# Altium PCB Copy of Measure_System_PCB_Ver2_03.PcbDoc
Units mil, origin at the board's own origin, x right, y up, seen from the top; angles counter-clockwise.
Board outline 6000 x 4000 mil, 2 copper layers (Top Layer, Bottom Layer); 49 components, 31 nets, 143 pads, 5 vias.
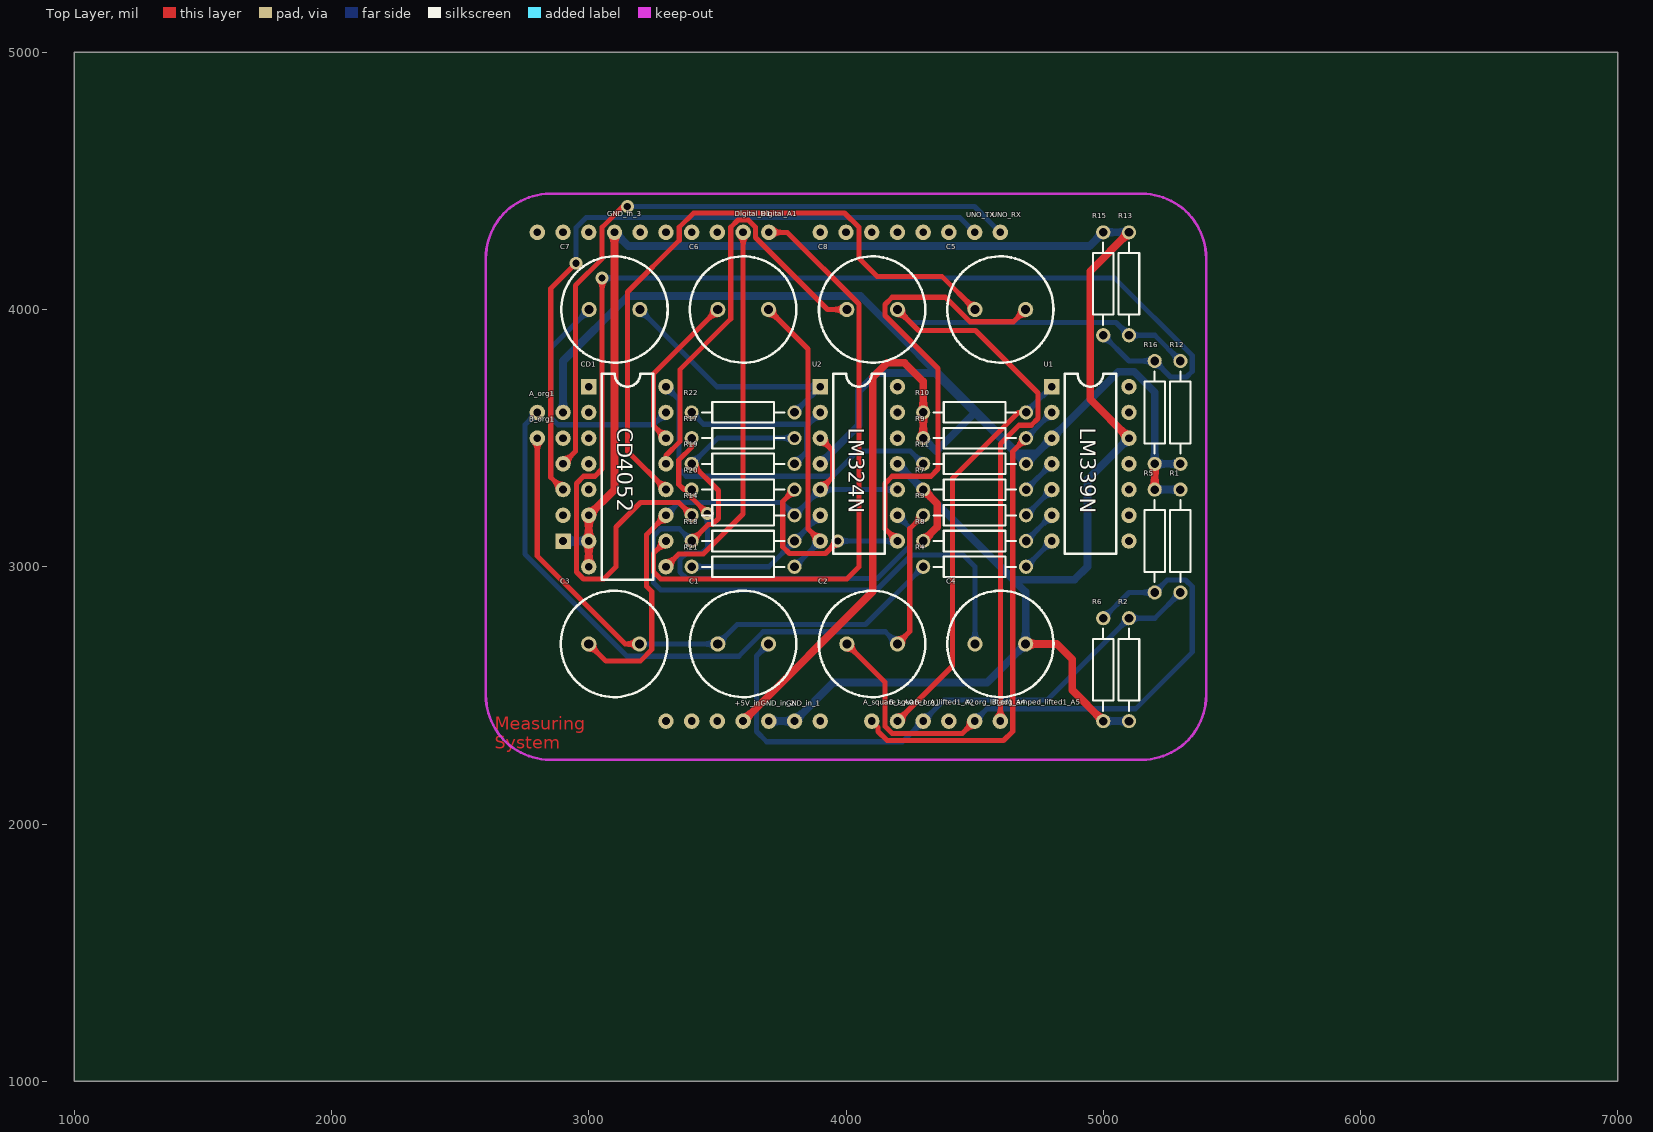
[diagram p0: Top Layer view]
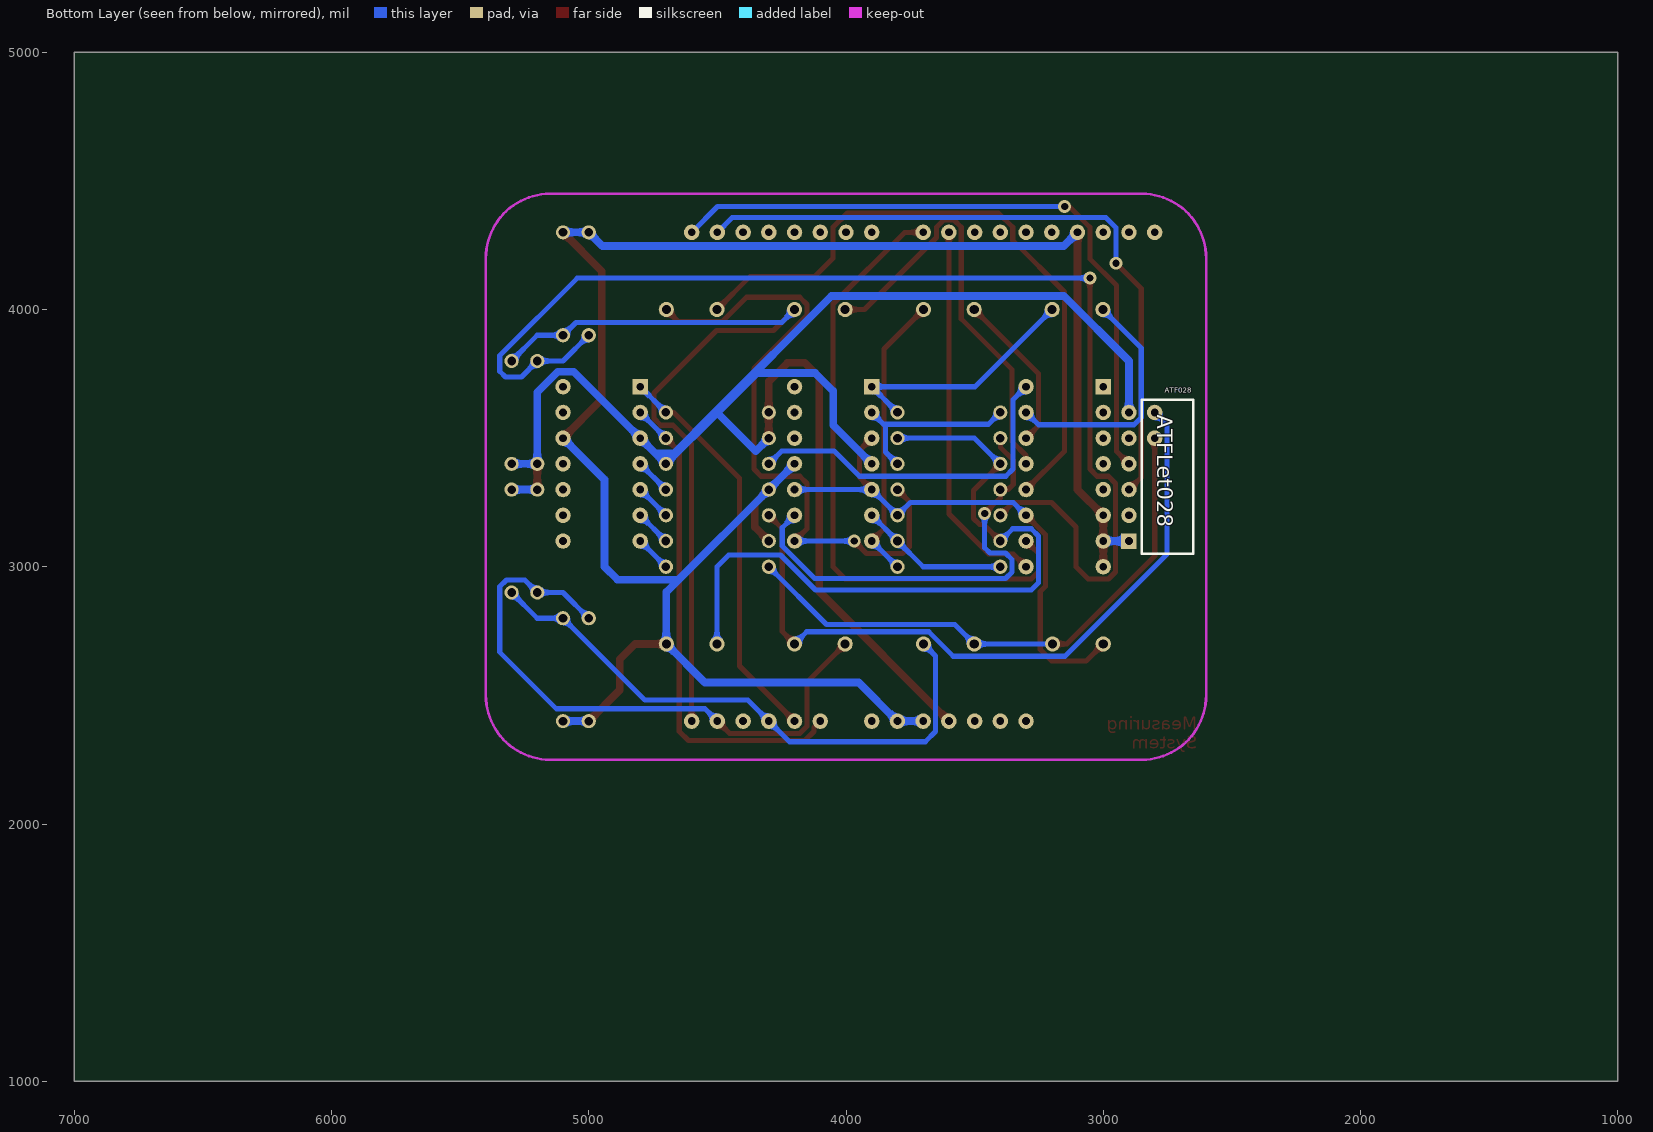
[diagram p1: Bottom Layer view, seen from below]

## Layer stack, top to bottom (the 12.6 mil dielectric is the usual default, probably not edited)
Top Solder: solder mask 0.4, Solder Resist, Dk 3.5
Top Layer: signal copper 1.4
Dielectric 1: dielectric 12.6, FR-4, Dk 4.8
Bottom Layer: signal copper 1.4
Bottom Solder: solder mask 0.4, Solder Resist, Dk 3.5

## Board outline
1000,1000 7000,1000 7000,5000 1000,5000

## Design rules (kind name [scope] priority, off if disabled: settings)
Clearance [All] p1: gap=7.87 ignorepadtopadclearanceinfootprint=FALSE
PolygonConnect [All] p1: connectstyle=Relief reliefconductorwidth=10 reliefentries=4 polygonreliefangle="90 Angle" airgapwidth=10
RoutingVias [All] p1: holewidth=28 width=50 viastyle="Through Hole" minholewidth=28 minwidth=50 maxholewidth=28 maxwidth=50
SolderMaskExpansion [All] p1: expansion=4 istentingtop=FALSE
Width Width_2 [InNet('GND')] p1: maxlimit=50 minlimit=10 preferedwidth=30 minimp=50.000000 maximp=50.000000 favimp=50.000000
Width Width_1 [InNet('+5')] p2: maxlimit=50 minlimit=10 preferedwidth=30 minimp=50.000000 maximp=50.000000 favimp=50.000000
Width [All] p3: maxlimit=50 minlimit=10 preferedwidth=20
30 further rules are at their usual default settings.

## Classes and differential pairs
component class Part_Square: C1 C2 R1 R2 R3 R4 R5 R6 R7 R8 R9 R10 U1
component class Part_PGA: C3 C4 C5 C6 C7 C8 CD1 R11 R12 R13 R14 R15 R16 R17 R18 R19 R20 R21 R22 U2
component class Measure_System_Main: +5V_in A_org1 A_org_lifted1_A4 A_square1_A0 ATF028 B_org1 B_org_amped_lifted1_A5 B_org_lifted1_A2 B_square1_A1 Digital_A1 Digital_B1 GND_in_1 GND_in_2 GND_in_3 UNO_RX UNO_TX

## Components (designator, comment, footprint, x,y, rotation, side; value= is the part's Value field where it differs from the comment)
+5V_in "Hole" Hole 3600,2400 r90 top
A_org1 "Hole" Hole 2800,3600 r90 top
A_org_lifted1_A4 "Hole" Hole 4500,2400 r90 top
A_square1_A0 "Hole" Hole 4100,2400 r90 top
ATF028 "ATFLet028" ATFLet028 2900,3600 r180 bottom
B_org1 "Hole" Hole 2800,3500 r90 top
B_org_amped_lifted1_A5 "Hole" Hole 4600,2400 r90 top
B_org_lifted1_A2 "Hole" Hole 4300,2400 r90 top
B_square1_A1 "Hole" Hole 4200,2400 r90 top
C1 "Cap Pol1" RB5-10.5 3600,2700 r0 top value=10u
C2 "Cap Pol1" RB5-10.5 4101.58,2700 r180 top value=10u
C3 "Cap Pol1" RB5-10.5 3098.43,2700 r180 top value=10u
C4 "Cap Pol1" RB5-10.5 4600,2700 r180 top value=10u
C5 "Cap Pol1" RB5-10.5 4600,4000 r180 top value=10u
C6 "Cap Pol1" RB5-10.5 3600,4000 r180 top value=10u
C7 "Cap Pol1" RB5-10.5 3100,4000 r180 top value=10u
C8 "Cap Pol1" RB5-10.5 4101.57,4000 r0 top value=10u
CD1 "CD4052" CD4052 3000,3700 r0 top
Digital_A1 "Hole" Hole 3700,4300 r90 top
Digital_B1 "Hole" Hole 3600,4300 r90 top
GND_in_1 "Hole" Hole 3800,2400 r90 top
GND_in_2 "Hole" Hole 3700,2400 r90 top
GND_in_3 "Hole" Hole 3100,4300 r90 top
R1 "Res2" AXIAL-0.4 5300,3100 r90 top value=100k
R2 "Res2" AXIAL-0.4 5100,2600 r90 top value=100k
R3 "Res2" AXIAL-0.4 4500,3200 r180 top value=1k
R4 "Res2" AXIAL-0.4 4500,3000 r180 top value=1k
R5 "Res2" AXIAL-0.4 5200,3100 r90 top value=100k
R6 "Res2" AXIAL-0.4 5000,2600 r90 top value=100k
R7 "Res2" AXIAL-0.4 4500,3300 r0 top value=10k
R8 "Res2" AXIAL-0.4 4500,3100 r180 top value=10k
R9 "Res2" AXIAL-0.4 4500,3500 r0 top value=10k
R10 "Res2" AXIAL-0.4 4500,3600 r180 top value=10k
R11 "Res2" AXIAL-0.4 4500,3400 r0 top value=200
R12 "Res2" AXIAL-0.4 5300,3600 r270 top value=100k
R13 "Res2" AXIAL-0.4 5100,4100 r270 top value=100k
R14 "Res2" AXIAL-0.4 3600,3200 r0 top value=100k
R15 "Res2" AXIAL-0.4 5000,4100 r270 top value=100k
R16 "Res2" AXIAL-0.4 5200,3600 r90 top value=100k
R17 "Res2" AXIAL-0.4 3600,3500 r180 top value=50k
R18 "Res2" AXIAL-0.4 3600,3100 r0 top value=24k
R19 "Res2" AXIAL-0.4 3600,3400 r0 top value=12k
R20 "Res2" AXIAL-0.4 3600,3300 r0 top value=100k
R21 "Res2" AXIAL-0.4 3600,3000 r0 top value=100k
R22 "Res2" AXIAL-0.4 3600,3600 r0 top value=100k
U1 "LM339N" LM339N 4800,3700 r0 top
U2 "LM324N" LM324N 3900,3700 r0 top
UNO_RX "Hole" Hole 4600,4300 r90 top
UNO_TX "Hole" Hole 4500,4300 r90 top

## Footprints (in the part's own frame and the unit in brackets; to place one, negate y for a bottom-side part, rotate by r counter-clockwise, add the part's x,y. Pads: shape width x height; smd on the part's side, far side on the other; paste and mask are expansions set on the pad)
ATFLet028 [mil]
  rect 60x60 hole 30: 1(0,-500)
  round 60 hole 30 mask+4: 2(0,-400) 3(0,-300) 4(0,-200) 5(0,-100) 6(0,0)
  silkscreen extent 50,-550 250,50
AXIAL-0.4 [mm] "Axial Device, Thru-Hole; 2 Leads; 0.4 in Pin Spacing"
  round 1.4 hole 0.85: 1(-5.08,0) 2(5.08,0)
  silkscreen extent -4.06,-1.02 4.06,1.02
CD4052 [mil]
  rect 60x60 hole 30: 1(0,0)
  round 60 hole 30 mask+4: 2(0,-100) 3(0,-200) 4(0,-300) 5(0,-400) 6(0,-500) 7(0,-600) 8(0,-700) 9(300,-700) 10(300,-600) 11(300,-500) 12(300,-400) 13(300,-300) 14(300,-200) 15(300,-100) 16(300,0)
  silkscreen extent 50,-750 250,50
Hole [mil]
  round 60 hole 30 mask+4: 1(0,0)
LM324N [mil]
  rect 60x60 hole 30: 1(0,0)
  round 60 hole 30 mask+4: 2(0,-100) 3(0,-200) 4(0,-300) 5(0,-400) 6(0,-500) 7(0,-600) 8(300,-600) 9(300,-500) 10(300,-400) 11(300,-300) 12(300,-200) 13(300,-100) 14(300,0)
  silkscreen extent 50,-650 250,50
LM339N [mil]
  rect 60x60 hole 30: 1(0,0)
  round 60 hole 30 mask+4: 2(0,-100) 3(0,-200) 4(0,-300) 5(0,-400) 6(0,-500) 7(0,-600) 8(300,-600) 9(300,-500) 10(300,-400) 11(300,-300) 12(300,-200) 13(300,-100) 14(300,0)
  silkscreen extent 50,-650 250,50
RB5-10.5 [mm] "Capacitor (Radial); 2 Leads"
  round 1.5 hole 0.9: 1(-2.5,0) 2(2.5,0)
  silkscreen extent -5.25,-5.25 5.25,5.25

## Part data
C1 C2 C3 C4 C5 C6 C7 C8: "Polarized Capacitor (Radial)"
R1 R2 R3 R4 R5 R6 R7 R8 R9 R10 R11 R12 R13 R14 R15 R16 R17 R18 R19 R20 R21 R22: "Resistor"

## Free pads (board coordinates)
  round 60 hole 30 mask+4: 5(4400,2400) 7(3900,2400) 8(3500,2400) 9(3400,2400) 10(3300,2400) 11(4400,4300) 12(4300,4300) 13(4200,4300) 14(4100,4300) 15(4000,4300) 16(3900,4300) 17(3500,4300) 18(3400,4300) 19(3300,4300) 20(3200,4300) 22(3000,4300) 23(2900,4300) 24(2800,4300)

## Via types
v1: diameter 50, hole 28, Top Layer to Bottom Layer, 5 vias

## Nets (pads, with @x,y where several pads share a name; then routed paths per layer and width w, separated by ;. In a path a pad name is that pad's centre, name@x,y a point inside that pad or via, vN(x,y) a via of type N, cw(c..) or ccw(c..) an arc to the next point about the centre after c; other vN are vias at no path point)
+5: +5V_in.1 ATF028.6 R1.2 R5.2 R9.1 R10.2 R11.2 R12.2 R16.1 U1.3 U2.4 | length 7134.3
  Top Layer w30: +5V_in.1 4104,2904 4104,3737 4160,3793 4227,3793 4300,3720 R10.2 R9.1 ; R5.2 R16.1
  Bottom Layer w30: ATF028.6 2900,3800 3153,4053 4056,4053 4505.5,3603.5 ; U2.4 4050,3550 4050,3683 4120,3753 4347,3753 4501,3599 ; R9.1 4351,3449 4501,3599 ; R5.2 R1.2 ; R12.2 R16.1 5200,3678 5120,3758 5058,3758 U1.3 4740,3440 ; 4501,3599 4505.5,3603.5 ; 4501,3599 R11.2 4740,3440 ; 4505.5,3603.5 4669,3440 4700,3440 4740,3440
B_org: B_org1.1 C1.1 C3.1 R4.2 | length 2223.9
  Top Layer w20: B_org1.1 2800,3042.09 3142.09,2700 C3.1
  Bottom Layer w20: C3.1 C1.1 3576.85,2775.28 4075.28,2775.28 R4.2
B_org_amp_1: C3.2 CD1.11 R14.2 U2.3 U2.5 U2.10 | length 2076
  Top Layer w20: C3.2 3067,2633 3200,2633 3245,2678 3245,2903.5 3224.25,2924.25 3224.25,3124.25 CD1.11 ; U2.5 3948,3348 3948,3452 U2.3
  Bottom Layer w20: CD1.11 3350.08,3250.08 3749.92,3250.08 R14.2 U2.5 U2.10
B_org_amp_2.5: C5.2 CD1.12 | length 2564.2
  Top Layer w20: CD1.12 3151,3449 3151,4068 3352,4269 3352,4320 3407.75,4375.75 3994.25,4375.75 4050,4320 4050,4199 4120,4129 4372.57,4129 C5.2
B_org_amp_5: C6.2 CD1.14 | length 623.3
  Top Layer w20: CD1.14 3252,3548 3252,3750.43 C6.2
B_org_amp_10: C7.2 CD1.15 | length 961.4
  Bottom Layer w20: C7.2 2852,3850.42 2852,3580 2880,3552 3252,3552 CD1.15
B_org_amped: C8.1 CD1.13 | length 1654.6
  Top Layer w20: CD1.13 3300,3432.29 3354,3486.29 3354,3766 3552,3964 3552,4320 3579.87,4347.87 3620.13,4347.87 3648,4320 3648,4280 3928,4000 C8.1
Digital_A: CD1.10 Digital_A1.1 | length 2457.8
  Top Layer w20: CD1.10 3252.13,3052.13 3252.13,2979.87 3280,2952 4003,2952 4051,3000 4051,4021 3772,4300 Digital_A1.1
Digital_B: CD1.9 Digital_B1.1 | length 1479.9
  Top Layer w20: CD1.9 3350,3050 3445,3050 3600,3205 Digital_B1.1
GND: ATF028.1 C4.1 CD1.6 CD1.7 CD1.8 GND_in_1.1 GND_in_2.1 GND_in_3.1 R2.1 R6.1 R7.1 R8.2 R13.1 R15.1 U1.12 U2.11 | length 8156.5
  Top Layer w30: CD1.8 CD1.7 CD1.6 3100,3300 GND_in_3.1 ; R8.2 4355,3155 4355,3245 R7.1 ; C4.1 4819,2700 4879,2640 4879,2521 R6.1 ; U1.12 4949,3651 4949,4149 R13.1
  Bottom Layer w30: ATF028.1 CD1.7 ; GND_in_3.1 3153,4247 4947,4247 R15.1 R13.1 ; GND_in_2.1 GND_in_1.1 3950,2550 4548.43,2550 C4.1 4698.43,2901.57 4651,2949 ; U2.11 R7.1 4651,2949 ; R6.1 R2.1 ; U1.12 4939,3339 4939,3000 4888,2949 4651,2949
NetA_org1_1: A_org1.1 C2.1 R3.2 | length 2783.9
  Top Layer w20: C2.1 4248,2748 4248,3148 R3.2
  Bottom Layer w20: A_org1.1 2752,3552 2752,3049 3149,2652 3583,2652 3678.4,2747.4 4152.6,2747.4 C2.1
NetA_org_lifted1_A4_1: A_org_lifted1_A4.1 C2.2 R5.1 R6.2 | length 2391.5
  Top Layer w20: C2.2 4152.13,2551.02 4152.13,2380 4180,2352.13 4452.13,2352.13 A_org_lifted1_A4.1
  Bottom Layer w20: A_org_lifted1_A4.1 4548,2448 5126,2448 5346,2668 5346,2923 5320,2949 5249,2949 R5.1 5100,2900 R6.2
NetA_square1_A0_1: A_square1_A0.1 R9.2 U1.2 | length 1906.4
  Top Layer w20: A_square1_A0.1 4124.25,2375.75 4124.25,2360 4160,2324.25 4612.25,2324.25 4648,2360 4648,3448 R9.2
  Bottom Layer w20: R9.2 U1.2
NetATF028_3: ATF028.3 UNO_TX.1 | length 2668.2
  Top Layer w20: ATF028.3 2852,3348 2852,4082 v1(2950,4180)
  Bottom Layer w20: v1(2950,4180) 2950,4317.7 2989.42,4357.13 4442.87,4357.13 UNO_TX.1
NetATF028_4: ATF028.4 UNO_RX.1 | length 2605.3
  Top Layer w20: ATF028.4 2947.87,3447.87 2947.87,4092.87 3052.13,4197.13 3052.13,4319.83 3132.3,4400 v1(3150,4400)
  Bottom Layer w20: v1(3150,4400) 4500,4400 UNO_RX.1
NetB_org_amped_lifted1_A5_1: B_org_amped_lifted1_A5.1 C8.2 R12.1 R13.2 | length 3227.1
  Top Layer w20: C8.2 4281.37,3918.63 4503.37,3918.63 4746,3676 4746,3576 4720,3550 4673,3550 4600,3477 B_org_amped_lifted1_A5.1
  Bottom Layer w20: C8.2 4250,3950 5050,3950 R13.2 5200,3900 R12.1
NetB_org_lifted1_A2_1: B_org_lifted1_A2.1 C1.2 R1.1 R2.2 | length 2264
  Bottom Layer w20: C1.2 3652,2653.57 3652,2360 3692,2320 4220,2320 B_org_lifted1_A2.1 4382,2482 4782,2482 R2.2 5200,2800 R1.1
NetB_square1_A1_1: B_square1_A1.1 R10.1 U1.1 | length 1566.1
  Top Layer w20: B_square1_A1.1 4414,2614 4414,3344 4670,3600 R10.1
  Bottom Layer w20: R10.1 U1.1
NetC4_2: C4.2 R17.1 R18.1 R19.1 | length 2834.8
  Top Layer w20: R18.1 3464.13,3164.13 3480,3164.13 3503.87,3188 3503.87,3296.13 R19.1
  Bottom Layer w20: R18.1 3352,3148 3280,3148 3252,3120 3252,2938 3280,2910 4119,2910 4255,3046 4455.57,3046 4501.57,3000 C4.2 ; R19.1 3500,3500 R17.1
NetC5_1: C5.1 R20.2 U2.8 | length 2533.3
  Top Layer w20: R20.2 3754,3254 3754,3078 3780,3052 3920,3052 v1(3968,3100) ; U2.8 4152,3148 4152,3324 4180,3352 4330,3352 4358,3380 4358,3771 4152,3977 4152,4020 4180,4048 4386.54,4048 4481.94,3952.6 4651.02,3952.6 C5.1
  Bottom Layer w20: v1(3968,3100) U2.8
NetC6_1: C6.1 R21.2 U2.7 | length 1124.9
  Top Layer w20: C6.1 3852,3846.43 3852,3148 U2.7
  Bottom Layer w20: R21.2 U2.7
NetC7_1: C7.1 R22.2 U2.1 | length 967.3
  Bottom Layer w20: C7.1 3498.43,3700 U2.1 R22.2
NetCD1_16: CD1.16 R11.1 | length 1363
  Bottom Layer w20: CD1.16 3351,3649 3351,3380 3379,3352 3948,3352 4046,3450 4250,3450 R11.1
NetR3_1: R3.1 U1.5 | length 141.4
  Bottom Layer w20: R3.1 U1.5
NetR4_1: R4.1 U1.7 | length 141.4
  Bottom Layer w20: R4.1 U1.7
NetR7_2: R7.2 U1.4 | length 141.4
  Bottom Layer w20: R7.2 U1.4
NetR8_1: R8.1 U1.6 | length 141.4
  Bottom Layer w20: R8.1 U1.6
NetR14_1: R14.1 R15.2 R16.2 | length 4805.7
  Top Layer w20: v1(3052,4122) 3052,3380 3024.13,3352.13 2980,3352.13 2952,3324.13 2952,2980 2980,2952 3058,2952 3106,3000 3106,3155 3201,3250 3350,3250 R14.1
  Bottom Layer w20: v1(3052,4122) 5045,4122 5346,3821 5346,3760 5324,3738 5262,3738 R16.2 5100,3800 R15.2
NetR17_2: R17.2 R20.1 U2.9 | length 1780.4
  Top Layer w20: R17.2 3400,3464.81 3350,3414.81 3350,3320 3370,3300 R20.1 3400,3268 v1(3461,3207)
  Bottom Layer w20: v1(3461,3207) 3461,3074 3440,3053 3380,3053 3354,3027 3354,2980 3380,2954 4121.71,2954 4248,3080.29 4248,3152 U2.9
NetR18_2: R18.2 R21.1 U2.6 | length 582.8
  Bottom Layer w20: R21.1 3700,3000 R18.2 U2.6
NetR19_2: R19.2 R22.1 U2.2 | length 711.2
  Bottom Layer w20: R22.1 3446,3554 3846,3554 ; R19.2 3846,3446 3846,3554 ; U2.2 3854,3554 3846,3554
pads on no net: ATF028.2 ATF028.5 CD1.1 CD1.2 CD1.3 CD1.4 CD1.5 U1.8 U1.9 U1.10 U1.11 U1.13 U1.14 U2.12 U2.13 U2.14

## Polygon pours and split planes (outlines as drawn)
no net on Bottom Layer "NONET_L-01_P-001" (solid, remove dead copper, pour order 0): 2500,4410

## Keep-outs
Keep-Out Layer:
  lines w10: 2600,2500 ccw(c2850,2500) 2850,2250 5150,2250 ccw(c5150,2500) 5400,2500 5400,4200 ccw(c5150,4200) 5150,4450 2850,4450 ccw(c2850,4200) 2600,4200 2600,2500

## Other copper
Top Layer:
  text "Measuring / System" at 2635.08,2292.03 h50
